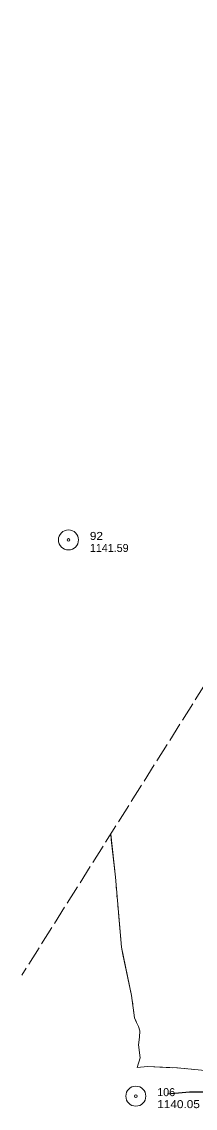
# Model space of a CAD drawing. Extents: x 298072 to 300359, y 47756 to 50122.
# Drawn here: x 298726 to 298855, y 48509 to 49323 of the extents above; entities that cross this region are included whole.
import ezdxf

# ---------------------------------------------------------------- set-up
doc = ezdxf.new("R2010")
doc.units = 0
doc.header["$LTSCALE"] = 2.4
doc.linetypes.add('LONG_DASHED', pattern=[7.5, 6, -1.5])
for name, color, linetype, lineweight in [('11', 7, 'Continuous', 25), ('19', 7, 'Continuous', 13), ('4', 7, 'Continuous', 13), ('6', 7, 'Continuous', 13)]:
    doc.layers.add(name, color=color, linetype=linetype, lineweight=lineweight)

msp = doc.modelspace()

# ---------------------------------------------------------------- linework, layer by layer
at = {"layer": '11'}
msp.add_lwpolyline([(298834.58, 48519.541), (298851.237, 48520.95), (298874.257, 48521.052)], dxfattribs=at)
at = {"layer": '19'}
for p, q in [((298792.662, 48710.204), (298792.223, 48714.261)), ((298796.528, 48672.433), (298796.345, 48674.596)), ((298797.074, 48665.947), (298796.892, 48668.109)), ((298797.621, 48659.461), (298797.439, 48661.623)), ((298808.708, 48586.662), (298808.424, 48588.813)), ((298809.558, 48580.21), (298809.275, 48582.361)), ((298811.199, 48573.993), (298810.304, 48575.961)), ((298847.21, 48538.432), (298849.021, 48538.264)), ((298852.643, 48537.928), (298854.454, 48537.759))]:
    msp.add_line(p, q, dxfattribs=at)
for points in [[(298811.934, 48539.27), (298814.124, 48546.474), (298813.089, 48556.134), (298813.719, 48562.039), (298814.065, 48566.715), (298813.065, 48569.904), (298811.621, 48573.066), (298810.043, 48576.534), (298807.832, 48593.303), (298800.151, 48629.446), (298795.736, 48681.825), (298792.222, 48714.261)], [(298795.981, 48678.92), (298795.736, 48681.825), (298792.662, 48710.204)], [(298801.332, 48623.89), (298800.151, 48629.446), (298797.986, 48655.137)], [(298807.857, 48593.114), (298807.832, 48593.303), (298801.332, 48623.89)], [(298811.934, 48539.27), (298814.124, 48546.474), (298813.089, 48556.134), (298813.719, 48562.039), (298814.065, 48566.715), (298813.065, 48569.904), (298812.992, 48570.064)], [(298811.934, 48539.27), (298819.663, 48539.989), (298842.165, 48538.9), (298875.536, 48535.803), (298909.762, 48532.409), (298943.635, 48530.51), (299012.386, 48526.339), (299045.94, 48524.905), (299065.344, 48525.656), (299080.022, 48527.572), (299090.397, 48526.576), (299095.491, 48526.071), (299097.133, 48525.348), (299095.618, 48521.498), (299095.393, 48520.904)], [(298811.934, 48539.27), (298819.663, 48539.989), (298838.143, 48539.095)], [(298841.775, 48538.919), (298842.165, 48538.9), (298843.587, 48538.768)]]:
    msp.add_lwpolyline(points, dxfattribs=at)
at = {"layer": '4', "linetype": 'LONG_DASHED'}
msp.add_line((299332.839, 49573.576), (298725.651, 48608.445), dxfattribs=at)
at = {"layer": '6'}
for centre, radius in [((298760.596, 48934.725), 7.5), ((298760.596, 48934.725), 0.96), ((298811.001, 48517.751), 7.5), ((298811.001, 48517.751), 0.96)]:
    msp.add_circle(centre, radius, dxfattribs=at)

# ---------------------------------------------------------------- texts
at = {"layer": '6', "width": 1.1}
for s, p in [('92', (298776.596, 48934.725)), ('1140.05', (298827.001, 48508.751))]:
    msp.add_text(s, height=6, dxfattribs=at).set_placement(p)
at = {"layer": '6'}
for s, p in [('1141.59', (298776.596, 48925.725)), ('106', (298827.001, 48517.751))]:
    msp.add_text(s, height=6, dxfattribs=at).set_placement(p)

doc.saveas('drawing.dxf')
